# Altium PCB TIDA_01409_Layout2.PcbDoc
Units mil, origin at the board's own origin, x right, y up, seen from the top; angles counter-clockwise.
Board outline 2000 x 1250 mil, 2 copper layers (Top Layer, Bottom Layer), stack 62 mil thick; 42 components, 23 nets, 118 pads, 92 vias.
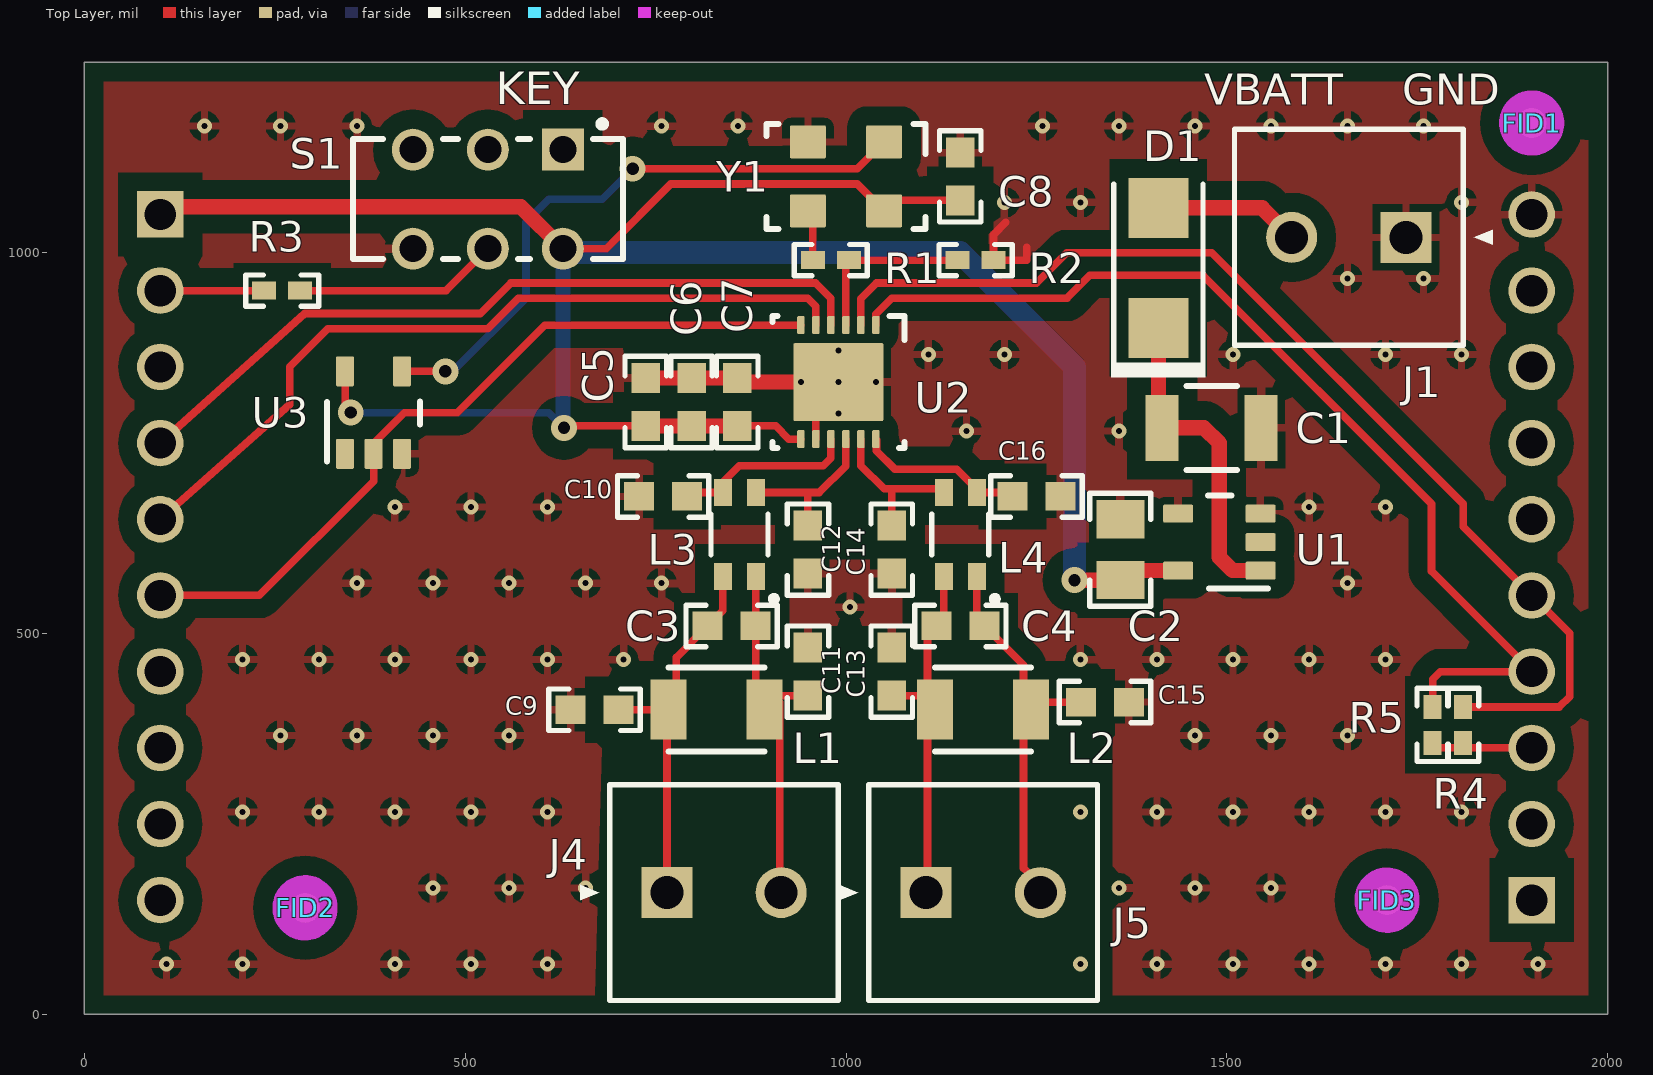
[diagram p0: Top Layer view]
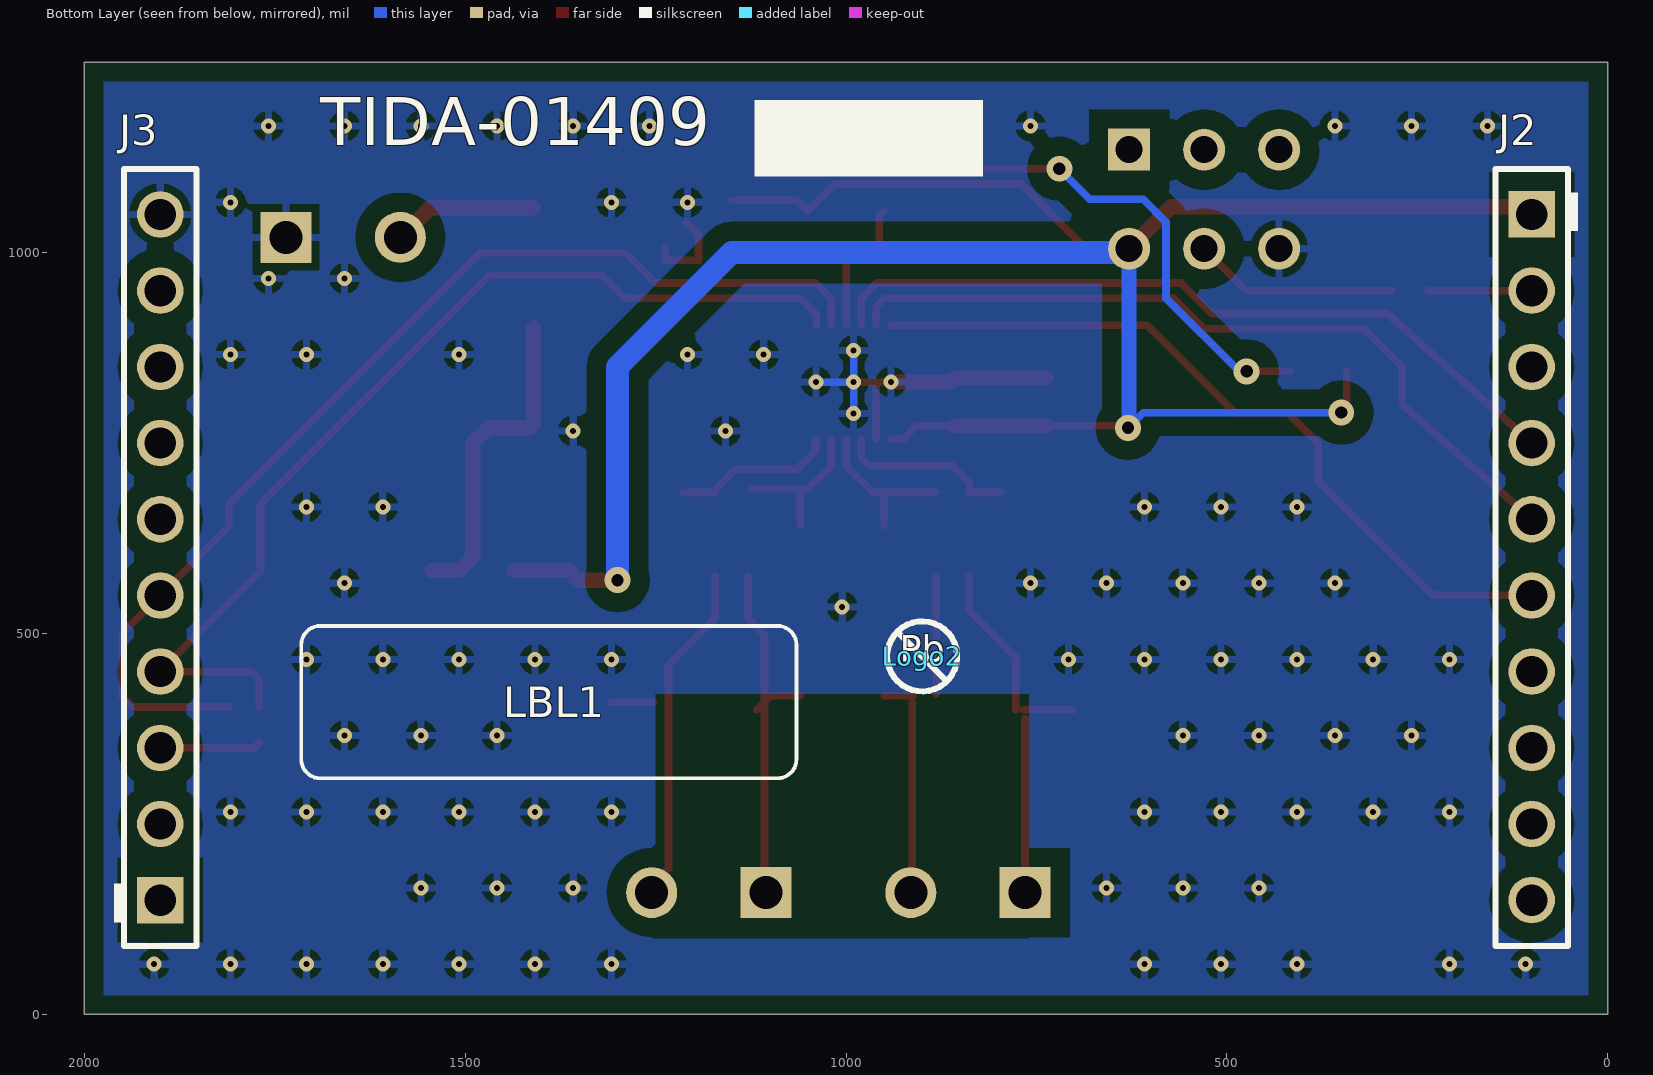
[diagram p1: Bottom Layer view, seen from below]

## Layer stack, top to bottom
Top Solder: solder mask 0.4, Solder Resist, Dk 3.5
Top Layer: signal copper 1.4
Dielectric1: core 59.2, FR-4, Dk 4.8
Bottom Layer: signal copper 1.4
Bottom Solder: solder mask 0.4, Solder Resist, Dk 3.5

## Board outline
0,0 0,1250 2000,1250 2000,0

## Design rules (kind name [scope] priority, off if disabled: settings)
AcuteAngle [All] p1: minimum=4.50000000000000E+0001 checktracksonly=FALSE
AssemblyTestPointUsage [All] p1: valid=2
BoardOutlineClearance BoardOutlineClearance_MountingHoles [OnCopper and InComponentClass('Mounting Holes')] p1: gap=40
BoardOutlineClearance BoardOutlineClearance_Poly [OnCopper and IsPoly] p2: gap=25
BoardOutlineClearance [OnCopper and Not InComponentClass('Logo') and not InComponentClass('FiducialMark') and not InRegion(1000,500,4000,800) and not InPoly] p3: gap=75
Clearance Clearance_Keepouts [((IsTrack Or IsArc) And Not InPoly) And IsFree and IsKeepOut vs ((IsTrack Or IsArc) And Not InPoly) And IsFree and IsKeepOut] p1: gap=0
Clearance Clearance_Poly [InPolygon] p2: gap=25
Clearance [All] p3: gap=7.87
ComponentClearance ComponentClearance_MountingHoles_FiducialMarks [InComponentClass('Mounting Holes') vs InComponentClass('FiducialMark')] p1: gap=50 collisioncheckmode=3 verticalgap=10 showdistances=FALSE
ComponentClearance ComponentClearance_Shunt [InComponentClass('Header') vs InComponentClass('Shunt')] p2: gap=0 collisioncheckmode=3 verticalgap=0 showdistances=FALSE
ComponentClearance ComponentClearance_Logo [InComponentClass('Logo')] p3: gap=50 collisioncheckmode=3 verticalgap=10 showdistances=FALSE
ComponentClearance ComponentClearance_ScrewToNut [(HasFootprint('NY PMS 440 0025 PH')) vs (HasFootprint('Keystone_1902C'))] p4: gap=5 collisioncheckmode=3 verticalgap=10 showdistances=FALSE
ComponentClearance ComponentClearance_MountingHoles [InComponentClass('Mounting Holes')] p5: gap=250 collisioncheckmode=3 verticalgap=100000 showdistances=FALSE
ComponentClearance ComponentClearance_SmallPassives [HasFootprint('0201*') or HasFootprint('0402*') or HasFootprint('0508') or HasFootprint('0603*') or HasFootprint('0612') or HasFootprint('0805*') or HasFootprint('0815*') or HasFootprint('0830*') or HasFootprint('1206*') or HasFootprint('1210*') or HasFootprint('1808*') or HasFootprint('1812*') or HasFootprint('1825*') or HasFootprint('2010*') or HasFootprint('2220*') or HasFootprint('2225*') or HasFootprint('2512*') or HasFootprint('2728*') or HasFootprint('3518*') vs HasFootprint('0201*') or HasFootprint('0402*') or HasFootprint('0508') or HasFootprint('0603*') or HasFootprint('0612') or HasFootprint('0805*') or HasFootprint('0815*') or HasFootprint('0830*') or HasFootprint('1206*') or HasFootprint('1210*') or HasFootprint('1808*') or HasFootprint('1812*') or HasFootprint('1825*') or HasFootprint('2010*') or HasFootprint('2220*') or HasFootprint('2225*') or HasFootprint('2512*') or HasFootprint('2728*') or HasFootprint('3518*')] p6: gap=14.96 collisioncheckmode=3 verticalgap=10 showdistances=FALSE
ComponentClearance ComponentClearance_THtoSMT [IsThruComponent vs IsSMTComponent] p7: gap=40 collisioncheckmode=3 verticalgap=30 showdistances=FALSE
ComponentClearance ComponentClearance_THtoTH [IsThruComponent vs IsThruComponent] p8: gap=30 collisioncheckmode=3 verticalgap=30 showdistances=FALSE
ComponentClearance [All] p9: gap=30 collisioncheckmode=3 verticalgap=10 showdistances=FALSE
DiffPairsRouting [All] p1: maxlimit=100 minlimit=10 mostfreqgap=10 toplayer_minwidth=15 toplayer_maxwidth=15 toplayer_prefwidth=15 bottomlayer_minwidth=15 bottomlayer_maxwidth=15 bottomlayer_prefwidth=15 maxuncoupledlength=1000
FabricationTestPointUsage TestPointUsage [All] p1: valid=2 allowmultiple=FALSE
FabricationTestpoint Testpoint [All] p1: side=3 testpointundercomponent=TRUE minsize=40 maxsize=100 preferedsize=60 minholesize=0 maxholesize=40 preferedholesize=32 testpointgrid=1 allowsidetop=TRUE allowsidebottom=TRUE usegrid=TRUE gridtolerance=0.01
FanoutControl Fanout_LCC [IsLCC] p1: bgadir=Out bgaviamode=Centered fanoutstyle=Auto fanoutdirection=Alternating viagrid=1 // Fanout_LCC (Default Rule)
FanoutControl Fanout_BGA [IsBGA] p2: bgadir=Out bgaviamode=Centered fanoutstyle=Auto fanoutdirection=Alternating viagrid=1 // Fanout_BGA (Default Rule)
FanoutControl Fanout_Default [All] p4: bgadir=Out bgaviamode=Centered fanoutstyle=Auto fanoutdirection=Alternating viagrid=1 // Fanout_Default (Default Rule)
FanoutControl Fanout_Small [(CompPinCount < 5)] p5: bgadir=Out bgaviamode=Centered fanoutstyle=Auto fanoutdirection=OutThenIn viagrid=1 // Fanout_Small (Default Rule)
HoleSize [All] p1: absolutevalues=TRUE maxlimit=251 minlimit=7.87 maxpercent=80.000 minpercent=20.000
MinimumAnnularRing MinimumAnnularRing_ThermalPadVias [IsVia and InAnyComponent] p1: minimumring=5.91
MinimumAnnularRing [All] p2: minimumring=8
MinimumSolderMaskSliver MinimumSolderMaskSliver_Logo [InComponentClass('Logo') vs InComponentClass('Logo')] p1: minsoldermaskwidth=0.7
MinimumSolderMaskSliver [All] p2: minsoldermaskwidth=3.94
PlaneConnect [All] p1: planeconnectstyle=Relief reliefexpansion=10 reliefentries=4 reliefconductorwidth=10 reliefairgap=10
PolygonConnect [All] p1: connectstyle=Relief reliefconductorwidth=10 reliefentries=4 polygonreliefangle="90 Angle" airgapwidth=10
RoutingVias ThermalPadVias [IsVia and InAnyComponent] p1: holewidth=7.87 width=19.68 viastyle="Through Hole" minholewidth=7.87 minwidth=19.68 maxholewidth=12.99 maxwidth=23.62
RoutingVias [All] p2: holewidth=16 width=34 viastyle="Through Hole" minholewidth=7.87 minwidth=26 maxholewidth=40 maxwidth=65
SilkToBoardRegionClearance [Not ((IsComment or IsDesignator) And (Hide <> 'False')) and not InRegion(1000,500,4000,800)] p1:
SilkToSilkClearance SilkToSilkClearance_Pb-FreeLogo [(HasFootprint('Pb-Free_Overlay_Medium') OR HasFootprint('Pb-Free_Overlay_Small')) vs (HasFootprint('Pb-Free_Overlay_Medium') OR HasFootprint('Pb-Free_Overlay_Small'))] p1: silktosilkclearance=0
SilkToSilkClearance [All] p2: silktosilkclearance=4
SilkToSolderMaskClearance SilkToComponentPadClearance [(IsPad or IsFill or IsRegion) and InAnycomponent] p1: minsilkscreentomaskgap=5 clearancetoexposedcopper=TRUE
SilkToSolderMaskClearance "Silk to Solder Mask Opening" [All] p2: minsilkscreentomaskgap=4 clearancetoexposedcopper=FALSE
SolderMaskExpansion [All] p1: expansion=1.97
Width [All] p1: maxlimit=100 minlimit=6 preferedwidth=10 checkconnectedcopper=TRUE
15 further rules are at their usual default settings.

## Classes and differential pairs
component class TIDA_01409_Schematic2: C1 C2 C3 C4 C5 C6 C7 C8 C9 C10 C11 C12 C13 C14 C15 C16 D1 J1 J2 J3 J4 J5 L1 L2 L3 L4 R1 R2 R3 R4 R5 S1 U1 U2 U3 Y1
component class Label: LBL1
component class FiducialMark: FID1 FID2 FID3
component class PCB_Project_EVM_Hardware: FID1 FID2 FID3 LBL1 Logo2 Logo3

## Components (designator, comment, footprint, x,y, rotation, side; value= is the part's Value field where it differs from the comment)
C1 "UMK325AB7106KMHT" 1210_280 1480,770 r0 top
C2 "C2012X7R1A475M125AC" 0805_HV 1360,610 r90 top
C3 "CL10C330FB8NNNC" 0603 850,510 r0 top
C4 "CL10C330FB8NNNC" 0603 1150,510 r0 top
C5 "GRM188R70J105KA01D" 0603 737.27,804 r90 top
C6 "C0603C104K8RACTU" 0603 797.27,804 r90 top
C7 "0603ZC103KAT2A" 0603 857.27,804 r90 top
C8 "0603ZC103KAT2A" 0603 1150,1100 r90 top
C9 "GRM1885C2A180JA01D" 0603 670,400 r180 top
C10 "GRM1885C2A180JA01D" 0603 760,680 r180 top
C11 "GRM1885C2A180JA01D" 0603 950,450 r270 top
C12 "GRM1885C2A180JA01D" 0603 950,610 r90 top
C13 "GRM1885C2A180JA01D" 0603 1060,450 r90 top
C14 "GRM1885C2A180JA01D" 0603 1060,610 r270 top
C15 "GRM1885C2A180JA01D" 0603 1340,410 r180 top
C16 "GRM1885C2A180JA01D" 0603 1250,680 r180 top
D1 "BYS10-45HE3/TR" SMA 1410,980 r90 top
FID1 "Fiducial" Fiducial10-20 1900,1170 r0 top
FID2 "Fiducial" Fiducial10-20 290,140 r0 top
FID3 "Fiducial" Fiducial10-20 1710,150 r0 top
J1 "1727010" PhoenixConact_1727010 1660,1020 r180 top
J2 "SSW-110-01-T-S" Samtec_SSW-110-x1-x-S 100,600 r270 bottom
J3 "SSW-110-01-T-S" Samtec_SSW-110-x1-x-S 1900,600 r90 bottom
J4 "1727010" PhoenixConact_1727010 840,160 r0 top
J5 "1727010" PhoenixConact_1727010 1180,160 r0 top
L1 "CMH322522-180KL" CMH322522 830,400 r0 top
L2 "CMH322522-180KL" CMH322522 1180,400 r0 top
L3 "SRF3216-222Y" SRF3216 860,630 r180 top
L4 "SRF3216-222Y" SRF3216 1150,630 r180 top
LBL1 "Size: 0.65\" x 0.20 \"" Label_650x200 1390,410 r180 bottom
Logo2 "Pb-Free Symbol" Pb-Free_Overlay_Small 900,470 r180 bottom
Logo3 "FCC disclaimer" FCC_disclaimer 1820,1580 r0 top
R1 "ERJ-2GE0R00X" 0402 980,990 r180 top
R2 "CRCW04021K00JNED" 0402 1170,990 r180 top
R3 "CRCW04021K00JNED" 0402 260,950 r0 top
R4 "CRCW040210K0JNED" 0402 1810,380 r270 top
R5 "CRCW040210K0JNED" 0402 1770,380 r270 top
S1 "JS202011CQN" SW_JS202011CQN 530,1070 r270 top
U1 "TPS7B6933QDBVRQ1" DBV0005A_N 1490,620 r180 top
U2 "FDC2212QDNTRQ1" DNT0012B 990,830 r270 top
U3 "SN74LVC1G04QDBVRQ1" DBV0005A_N 380,790 r90 top
Y1 "DSC1001BI1-040.0000" Microchip_DSC1001BI1 1000,1100 r270 top

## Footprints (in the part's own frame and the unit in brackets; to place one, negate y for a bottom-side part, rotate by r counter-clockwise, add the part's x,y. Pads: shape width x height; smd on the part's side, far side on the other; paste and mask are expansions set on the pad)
0402 [mm] "0402 from SM-752 data"
  rect 0.8x0.6 smd: 1(-0.6,0) 2(0.6,0)
  silkscreen extent -1.22,-0.52 1.22,0.52, body extent -0.55,-0.3 0.55,0.3, height 0.6
0603 [mm] "0603 from SM-752 data"
  rect 1x0.95 smd: 1(-0.8,0) 2(0.8,0)
  silkscreen extent -1.52,-0.69 1.52,0.69, body extent -0.87,-0.47 0.87,0.47, height 1
0805_HV [mil] "0805 with 30mil clearance between pads"
  rect 50x63 smd: 1(-40,0) 2(40,0)
  silkscreen extent -74,-40 74,40, body extent -43,-29 43,29, height 57
1210_280 [mm] "SMD, 2-Leads, Body 3.6x2.8mm, Height 2.8mm"
  rect 1.1x2.2 smd: 1(-1.65,0) 2(1.65,0)
  silkscreen extent -0.84,-1.4 0.84,1.4, body extent -1.8,-1.4 1.8,1.4, height 2.8
CMH322522 [mm] "Bourns"
  rect 1.2x2 smd: 1(-1.6,0) 2(1.6,0)
  silkscreen extent -1.6,-1.4 1.6,1.4, body extent -1.7,-1.35 1.7,1.35, height 2.4
DBV0005A_N [mm] "SOT23, 5-Leads, Body 2.9x1.6mm, Pitch 0.95mm, Lead Span 2.8mm, IPC Medium Density"
  rrect17% 1x0.6 smd: 1(-1.375,0.95) 2(-1.375,0) 3(-1.375,-0.95) 4(1.375,-0.95) 5(1.375,0.95)
  silkscreen extent -1.63,-1.55 0.38,1.55, body extent -1.42,-1.46 1.42,1.46, height 1.09
DNT0012B [mm] "SON, 12-Leads, Body 4x4mm, Pitch 0.5mm"
  rrect40% 0.6x0.25 smd: 1(-1.9,1.25) 2(-1.9,0.75) 3(-1.9,0.25) 4(-1.9,-0.25) 5(-1.9,-0.75) 6(-1.9,-1.25) 7(1.9,-1.25) 8(1.9,-0.75) 9(1.9,-0.25) 10(1.9,0.25) 11(1.9,0.75) 12(1.9,1.25)
  rrect4% 2.6x3 smd paste-1.3: 13(0,0)
  silkscreen extent -2.2,-2.2 2.2,2.2, body extent -2,-2 2,2, height 0.81
FCC_disclaimer [mil]
Fiducial10-20 [mm]
  round 1 smd mask+0.5: 1(0,0)
  Top Layer keep-out circle w1.178: c0,0 r0.5
Label_650x200 [mil] "Thermal Transfer Label"
  silkscreen extent -325,-100 325,100, body extent -325,-100 325,100, height 1
Microchip_DSC1001BI1 [mm] "SMD, 4-Leads, Body 5x3.2mm"
  rrect9% 1.1x1.2 smd: 1(-1.15,1.27) 2(-1.15,-1.27) 3(1.15,-1.27) 4(1.15,1.27)
  silkscreen extent -1.75,-2.65 1.75,2.65, body extent -1.6,-2.5 1.6,2.5, height 0.91
Pb-Free_Overlay_Small [mil]
  silkscreen extent -46,-46 46,46
PhoenixConact_1727010 [mm]
  rect 1.7x1.7 hole 1.1: 1(-1.905,0)
  round 1.7 hole 1.1: 2(1.905,0)
  silkscreen extent -4.8,-3.6 3.81,3.6, body extent -3.81,-3.6 3.81,3.7, height 8.52
Samtec_SSW-110-x1-x-S [mm] "Receptacle, 2.54mm, 10x1, TH"
  rect 1.55x1.55 hole 1.04: 1(-11.43,0)
  round 1.55 hole 1.04: 2(-8.89,0) 3(-6.35,0) 4(-3.81,0) 5(-1.27,0) 6(1.27,0) 7(3.81,0) 8(6.35,0) 9(8.89,0) 10(11.43,0)
  silkscreen extent -12.95,-1.21 12.95,1.55, body extent -12.95,-1.21 12.95,1.21, height 8.51
SMA [mm] "Molded Diode, 2-Leads, Body 4.3x2.6mm, IPC Medium Density, based on OnSemi component dimensions and land pattern"
  rect 2x2 smd: 1(-2,0) 2(2,0)
  silkscreen extent -3.66,-1.57 2.79,1.57, body extent -2.6,-1.3 2.6,1.3, height 2.42
SRF3216 [mm] "BOURNS"
  rect 0.6x0.9 smd: 1(-0.55,1.4) 2(-0.55,-1.4) 3(0.55,-1.4) 4(0.55,1.4)
  silkscreen extent -1.25,-0.67 0.95,2.25, body extent -0.9,-1.7 0.9,1.7, height 2.21
SW_JS202011CQN [mm] "C&K components"
  rect 1.4x1.4 hole 0.9 paste+0: 1(-1.65,2.5)
  round 1.4 hole 0.9 paste+0: 2(-1.65,0) 3(-1.65,-2.5) 4(1.65,2.5) 5(1.65,0) 6(1.65,-2.5)
  silkscreen extent -2.61,-4.5 2,4.5, body extent -2,-4.5 2,4.5, height 5.5

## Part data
C1: "CAP, CERM, 10 µF, 50 V, +/- 10%, X7R, AEC-Q200 Grade 1, 1210"
C2: "CAP, CERM, 4.7 µF, 10 V, +/- 20%, X7R, 0805"
C3 C4: "CAP, CERM, 33 pF, 50 V, +/- 5%, C0G/NP0, 0603"
C5: "CAP, CERM, 1 µF, 6.3 V, +/- 10%, X7R, 0603"
C6: "CAP, CERM, 0.1 µF, 10 V, +/- 10%, X7R, 0603"
C7 C8: "CAP, CERM, 0.01 µF, 10 V, +/- 10%, X7R, 0603"
C9 C10 C11 C12 C13 C14 C15 C16: "CAP, CERM, 18 pF, 100 V, +/- 5%, C0G/NP0, 0603"
D1: "Diode, Schottky, 45 V, 1.5 A, AEC-Q101, SMA"
FID1 FID2 FID3: "Fiducial mark.  There is nothing to buy or mount."
J1 J4 J5: "Conn Term Block, 2POS, 3.81mm, TH"
J2 J3: "Receptacle, 2.54mm, 10x1, Tin, TH"
L1 L2: "Inductor, Shielded, Ferrite, 18 µH, 0.12 A, 3.3 ohm, SMD"
L3 L4: "Inductor, Wirewound, Ferrite, 0.2 A, 1.2 ohm, SMD"
LBL1: library part THT-14-423-10, "Thermal Transfer Printable Labels, 0.650\" W x 0.200\" H - 10,000 per roll"
Logo2: library part Pb-Free
Logo3: library part FCC_disclaimer, "FCC_disclaimer"
R1: "RES, 0, 5%, 0.063 W, 0402"
R2 R3: "RES, 1.0 k, 5%, 0.063 W, 0402"
R4 R5: "RES, 10 k, 5%, 0.063 W, 0402"
S1: "Slide Switch, DPDT, 0.3A 6VDC, TH"
U1: "High Voltage Ultra Low Iq - Low Drop Out Regulator, DBV0005A (SOT-5)"
U2: "Multi-Channel 12-Bit or 28-Bit Capacitance-to-Digital Converter (FDC) for Capacitive Sensing, DNT0012B (WSON-12)"
U3: "Automotive Catalog Single Inverter, DBV0005A (SOT-5)"
Y1: "OSC, 4MHz, CMOS, 1.8 to 3.3V, SMD"

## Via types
v1: diameter 19.68, hole 7.87, Top Layer to Bottom Layer, 87 vias
v2: diameter 34, hole 16, Top Layer to Bottom Layer, 5 vias

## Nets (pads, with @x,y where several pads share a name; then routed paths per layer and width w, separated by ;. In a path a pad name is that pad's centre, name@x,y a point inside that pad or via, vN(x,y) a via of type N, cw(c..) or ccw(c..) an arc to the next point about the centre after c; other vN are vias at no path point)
3P3V: C2.1 C5.1 C6.1 C7.1 C8.1 J2.1 S1.4 U1.5 U2.7 U3.5 Y1.4 | length 3181.6
  Top Layer w10: v2@342.6,802.6 U3.5 ; S1.4 685.04,1005.04 770,1090 1014.72,1090 Y1.4 1063.78,1068.5 C8.1 ; v2(630,770) 632.5,772.5 C5.1 ; C7.1 907.5,772.5 924.8,755.2 U2.7 ; C2.1 1350,570 C2.1@1362.6,582.6
  Top Layer w20: J2.1 110,1060 573.46,1060 S1.4 ; C5.1 C6.1 C7.1 ; v2(1300,570) C2.1@1350,570 ; C2.1@1362.6,582.6 U1.5
  Bottom Layer w10: v2(350,790) 610,790 628.43,771.57 v2(630,770) ; S1.4 S1.4@633.46,1000
  Bottom Layer w20: v2@628.43,771.57 S1.4
  Bottom Layer w30: S1.4@633.46,1000 1150,1000 1300,850 v2(1300,570)
ADDR: J2.4 U2.4 | length 1005.2
  Top Layer w10: J2.4 289.56,920 520,920 560,960 960,960 980.16,939.84 U2.4
GND: C1.2 C2.2 C5.2 C6.2 C7.2 C8.2 C9.2 C10.2 C11.1 C12.1 C13.2 C14.2 C15.1 C16.1 J1.1 J3.10 R2.1 S1.6 U1.3 U1.4 U2.8 U2.13 U3.3 Y1.2 | length 571.5
  Top Layer w10: v1(940.79,830) U2.13@960.47,830 ; U2.8 U2.13@960.47,830 ; v1(990,830) U2.13@960.47,830 ; 1209.88,1040 1193.62,1023.74 R2.1 1237.21,990 1237.21,1007.21
  Top Layer w20: C5.2 C6.2 C7.2 ; C7.2@862.76,830 v1(940.79,830)
  Bottom Layer w10: v1(990,788.66) v1(990,830) ; v1(990,871.34) v1(990,830) ; v1(1039.21,830) v1(990,830)
  other v1: 108,66 208,66 408,66 508,66 608,66 1308,66 1408,66 1508,66 1608,66 1708,66 1808,66 1908,66 458,166 558,166 658,166 1358,166 1458,166 1558,166 208,266 308,266 408,266 508,266 608,266 1308,266 1408,266 1508,266 1608,266 1708,266 1808,266 258,366 358,366 458,366 558,366 1458,366 1558,366 1658,366 208,466 308,466 408,466 508,466 608,466 708,466 1308,466 1408,466 1508,466 1608,466 1708,466 1005,535 358,566 458,566 558,566 658,566 758,566 1658,566 408,666 508,666 608,666 1608,666 1708,666 1158,766 1358,766 1108,866 1208,866 1508,866 1708,866 1808,866 1658,966 1758,966 1208,1066 1308,1066 1808,1066 158,1166 258,1166 358,1166 758,1166 858,1166 1258,1166 1358,1166 1458,1166 1558,1166 1658,1166 1758,1166
IN0A: C3.1 C9.1 J4.1 L1.1 L3.4 | length 483.8
  Top Layer w10: C9.1 L1.1 ; J4.1@765,170 L1.1@765,387.99 ; L1.1@777.01,400 777.01,468.5 C3.1 838.35,529.84 L3.4
IN0B: C3.2 C11.2 J4.2 L1.2 L3.1 | length 432.9
  Top Layer w10: L1.2@881.65,421.34 L3.1 ; L1.2@911.5,418.5 C11.2 ; L1.2@912.99,410 912.99,172.01 J4.2@915,170
IN1A: C4.1 C13.1 J5.1 L2.1 L4.4 | length 476.4
  Top Layer w10: C13.1 1098.5,418.5 L2.1@1107.01,410 ; J5.1@1107.01,172.01 L2.1@1107.01,410 ; L2.1 L2.1@1107.01,410 ; L4.4 1128.35,519.84 C4.1 1107.01,498.5 L2.1@1107.01,410
IN1B: C4.2 C15.2 J5.2 L2.2 L4.1 | length 494.9
  Top Layer w10: L4.1 1171.65,519.84 C4.2 1232.99,458.5 1232.99,192.01 J5.2@1255,170 ; L2.2@1252.99,410 C15.2
INTB: J2.5 U2.5 | length 1033.4
  Top Layer w10: J2.5 270,800.44 270,850 320,900 530,900 570,940 950,940 960.47,929.53 U2.5
KEY: J2.2 R3.1 | length 136.4
  Top Layer w10: J2.2 R3.1
NetC10_1: C10.1 L3.3 U2.9 | length 235
  Top Layer w10: C10.1@796.61,685.12 L3.3 838.35,698.35 860,720 970,720 980.16,730.16 U2.9
NetC12_2: C12.2 L3.2 U2.10 | length 211.5
  Top Layer w10: L3.2 950,685.12 ; C12.2 950,685.12 ; U2.10 999.84,719.84 965.12,685.12 950,685.12
NetC14_1: C14.1 L4.3 U2.11 | length 199.8
  Top Layer w10: U2.11 1019.53,720.47 1050,690 1060,690 ; C14.1 1060,690 ; L4.3@1123.46,690 1060,690
NetC16_2: C16.2 L4.2 U2.12 | length 209.8
  Top Layer w10: U2.12 1040,754.41 1040,740 1064.29,715.71 1145.49,715.71 L4.2@1171.65,689.55 ; L4.2 C16.2@1213.39,685.12
NetJ3_3: J3.3 R4.2 R5.2 | length 132.6
  Top Layer w10: R5.2 1776.38,350 J3.3
NetR1_1: R1.1 R2.2 U2.3 | length 229.5
  Top Layer w10: U2.3 999.84,986.22 R1.1 R2.2
NetR1_2: R1.2 Y1.3 | length 67.4
  Top Layer w10: Y1.3 956.38,1048.35 R1.2
NetR3_2: R3.2 S1.5 | length 269.2
  Top Layer w10: R3.2 474.96,950 S1.5
NetU3_4: U3.4 Y1.1 | length 815.9
  Top Layer w10: U3.4 v2(474.13,844.13) ; v2(720,1110) 1014.72,1110 Y1.1
  Bottom Layer w10: v2(474.13,844.13) 484.13,844.13 580,940 580,1040 610,1070 680,1070 v2(720,1110)
SCL: J3.4 R5.1 U2.1 | length 1353.7
  Top Layer w10: U2.1 1039.21,919.21 1060,940 1290,940 1320,970 1468.5,970 1768.5,670 1768.5,581.94 J3.4@1900.44,450 ; R5.1 1770,440 1780,450 J3.4
  Bottom Layer w10: J3.4@1900.44,450 J3.4@1900.44,469.56
SDA: J3.5 R4.1 U2.2 | length 1443.3
  Top Layer w10: U2.2 1019.53,939.53 1040,960 1250,960 1290,1000 1480,1000 1810,670 1810,640.44 1950,500.44 1950,417.24 1936.38,403.62 R4.1
SHUTDOWN: J2.6 U2.6 U3.2 | length 1017
  Top Layer w10: J2.6 230,550 380,700 U3.2 380,750 420,790 490,790 604.8,904.8 U2.6
VBATT: D1.2 J1.2 | length 191
  Top Layer w20: D1.2 1546.26,1058.74 J1.2
VIN: C1.1 D1.1 U1.1 | length 427.9
  Top Layer w10: C1.1@1410,775.04 C1.1
  Top Layer w20: C1.1@1410,775.04 D1.1 ; C1.1 1470,770 1490,750 1490,600 1507.4,582.6 U1.1
pads on no net: FID1.1 FID2.1 FID3.1 J2.3 J2.7 J2.8 J2.9 J2.10 J3.1 J3.2 J3.6 J3.7 J3.8 J3.9 S1.1 S1.2 S1.3 U1.2 U3.1

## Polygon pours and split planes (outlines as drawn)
GND on Bottom Layer "BOTTOM_LAYER_GND_P006" (solid, remove dead copper, pour order 6): 1980,20 1980,1230 20,1230 20,20 1980,20
GND on Top Layer "TOP_LAYER_GND_P008" (solid, remove dead copper, pour order 8): 20,20 20,1230 1980,1230 1980,20 20,20

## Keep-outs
Keep-Out Layer:
  text ".Layer_Name" at 577,-858.49 h60

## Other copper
Top Layer:
  pour cut-out: 1291.61,366.3 1291.61,21.61 1290,20 1350,20 1350,363.11 1353.19,366.3
  pour cut-out: 670,20 671.73,18.27 740,18.27 740,350 730,360 680,360
  pour cut-out: 978.7,596.81 1031.3,596.81 1031.3,688.7 1030,690 990,690 990,608.11
  pour cut-out: 977.27,509.98 1032.73,509.98 1032.73,362.73 1030,360 980,360 980,507.25
  pour cut-out: 1180,330 1290,330 1290,58.27 1330,18.27 1170,18.27 1170,320
  pour cut-out: 943.25,373.82 1068.39,373.82 1070,372.2 1070,350 1090,330 1076.75,316.75 1076.75,218.46 1046.54,218.46 1046.54,101.78 951.31,101.78 943.25,109.83
  pour cut-out: 690,18.27 690,85 706.78,101.78 1260.32,101.78 1260.32,87.95 1330,18.27
  text ".Layer_Name" at 577,-858.49 h60
Bottom Layer:
  pour cut-out: 790,420 760,420 760,410.41 760.41,410 790,410
  pour cut-out: 1255,101.25 1253.75,100 760,100 760,420 769.59,410.41 1250,410.41 1250,106.25
  pour cut-out: 1255,160 765,160 765,405 780,420 1250,420 1250,165
  text ".Layer_Name" at 577,-858.49 h60

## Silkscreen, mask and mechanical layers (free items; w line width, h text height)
Top Overlay:
  text "KEY" at 540,1180 h72.83
  text "VBATT" at 1470,1180 h70
  text "GND" at 1730,1180 h70
  text ".Layer_Name" at 577,-858.49 h60
Bottom Overlay:
  region: 1120,1200 820,1200 820,1100 1120,1100
  text "TIDA-01409" at 1690,1120 h108.27
  text ".Layer_Name" at 577,-858.49 h60
Top Paste:
  text ".Layer_Name" at 577,-858.49 h60
Bottom Paste:
  text ".Layer_Name" at 577,-858.49 h60
Top Solder:
  text ".Layer_Name" at 577,-858.49 h60
  text ".Layer_Name" at 577,-858.49 h60
Bottom Solder:
  text ".Layer_Name" at 577,-858.49 h60
Drill Guide:
  text ".Layer_Name" at 577,-858.49 h60
M1 Board Outline:
  the board outline again, w10
  text ".Layer_Name" at 577,-858.49 h60
M2 Board Dimensions:
  rectangle: 125,-400 500,-275
  rectangle: 0,-275 125,-150
  lines w7: 0,-275 1000,-275 ; 125,-400 125,-150 ; 250,-400 250,-150 ; 500,-400 500,-150 ; 750,-400 750,-150 ; 0,-400 0,-150 1000,-150 1000,-400 0,-400
  text ".Layer_Name" at 577,-858.49 h60
M3 3D STEP Top:
  text ".Layer_Name" at 577,-858.49 h60
M4 3D STEP Bottom:
  text ".Layer_Name" at 577,-858.49 h60
M5 Assembly Top:
  lines w10: -292,-930.17 6308,-930.17 ; -292,-726.83 6310,-726.83 ; -292,-523.5 -292,-1133.5 3713,-1133.5 6310,-1133.5 6310,-523.5 -291.5,-523.5 -291.5,-1133.5 1284,-1133.5 ; 2173,-1133.5 2173,-523.5 ; 3440,-726.83 3440,-523.5 ; 4280,-726.83 4280,-523.5 ; 4902,-1140 4902,-937.17
  text "COMPONENTS MARKED 'DNP' SHOULD NOT BE POPULATED." at 1153.5,-318.5 h60
  text "ASSEMBLY VARIANT:" at 1153,-434 h60
  text ".VariantName" at 2189,-434 h60
  text "PCB VIEWED FROM TOP SIDE" at -228.5,-655.67 h60
  text "BOARD #:" at 2248,-655.67 h60
  text ".PRJ_Number" at 2793.5,-655.67 h60
  text "REV:" at 3638,-655.67 h60
  text ".PCB_Rev" at 3929.5,-655.67 h60
  text "SVN REV:" at 4476,-655.67 h60
  text ".VersionControl_RevNumber" at 4982,-655.67 h60
  text "TID #:" at 2248,-859 h60
  text ".TID" at 2793.5,-859 h60
  text "PLOT NAME =" at -228.5,-1064.34 h60
  text ".plot_File_Name" at 577,-1064.34 h60
  text "GENERATED    :" at 2250,-1064.34 h60
  text ".Print_Date" at 3119.5,-1064.34 h60
  text ".Print_Time" at 3848.5,-1064.34 h60
  text "TEXAS INSTRUMENTS" at 5113,-1064.34 h60
M6 Assembly Bottom:
  lines w10: -292.5,-727.33 6309.5,-727.33 ; -290.5,-930.67 6309.5,-930.67 ; 1115.5,-1140.5 1115.5,-937.67 ; 1737.5,-727.33 1737.5,-524 ; 2577.5,-727.33 2577.5,-524 ; 3844.5,-1134 3844.5,-524 ; 4733.5,-1134 6309,-1134 6309,-524 -292.5,-524 -292.5,-1134 2304.5,-1134 6309.5,-1134 6309.5,-524
  text "COMPONENTS MARKED 'DNP' SHOULD NOT BE POPULATED." at 6102,-318 h60
  text ".VariantName" at 5058,-434 h60
  text "ASSEMBLY VARIANT:" at 6097,-434 h60
  text ".VersionControl_RevNumber" at 1035.5,-656.17 h60
  text "SVN REV:" at 1541.5,-656.17 h60
  text ".PCB_Rev" at 2088,-656.17 h60
  text "REV:" at 2379.5,-656.17 h60
  text ".PRJ_Number" at 3224,-656.17 h60
  text "BOARD #:" at 3769.5,-656.17 h60
  text "PCB VIEWED FROM BOTTOM SIDE" at 6246,-656.17 h60
  text ".TID" at 3224,-859.5 h60
  text "TID #:" at 3769.5,-859.5 h60
  text "TEXAS INSTRUMENTS" at 904.5,-1064.84 h60
  text ".Print_Time" at 2169,-1064.84 h60
  text ".Print_Date" at 2898,-1064.84 h60
  text "GENERATED    :" at 3767.5,-1064.84 h60
  text ".plot_File_Name" at 5440.5,-1064.84 h60
  text "PLOT NAME =" at 6246,-1064.84 h60
M9 Title Sheet:
  drawing of 57 lines, arcs and shapes, not listed
  text "1" at 739.84,8036.5 h70
  text "2" at 3235.5,8036.5 h70
  text "3" at 5724.84,8036.5 h70
  text "4" at 8231.51,8036.5 h70
  text "5" at 10730.5,8036.5 h70
  text "6" at 13235.5,8036.5 h70
  text "A" at -416.5,6893.5 h70
  text "A" at 14383.5,6893.5 h70
  text "B" at -416.5,4513.5 h70
  text "B" at 14383.5,4513.5 h70
  text "C" at -416.5,2138.5 h70
  text "C" at 14383.5,2138.5 h70
  text "PROJECT TITLE:" at 11343.5,277.5 h45
  text "Automotive Capacitive Kick-to-Open" at 11393.5,144.17 h70
  text "DESIGNED FOR:" at 11343.5,-23.5 h45
  text ".PRJ_Customer" at 11393.5,-163.5 h70
  text "D" at -416.5,-231.5 h70
  text "D" at 14383.5,-231.5 h70
  text "FILE NAME:" at 11343.5,-323.5 h45
  text ".PCB_File_Name_No_Path" at 11393.5,-443.5 h70
  text "Texas Instruments (TI) and/or its licensors do not warrant the accuracy or completeness of this specification" at 6374,-605.34 h45
  text "ENGINEER:" at 11343.5,-613.5 h45
  text "LAYOUT BY:" at 12848.5,-613.5 h45
  text "or any information contained therein. TI and/or its licensors do not warrant that this design will meet" at 6329.01,-718 h45
  text "C.Kinnaird" at 11393.5,-768.49 h70
  text "C.Kinnaird" at 12899,-768.49 h70
  text "the specifications, will be suitable for your application or fit for any particular purpose, or will operate in" at 6329.01,-830.67 h45
  text ".Layer_Name" at 577,-858.49 h60
  text "ALTIUM DESIGNER VERSION:" at 12848.5,-923.5 h45
  text "an implementation. TI and/or its licensors do not warrant that the design is production worthy. You should" at 6329.01,-943.33 h45
  text "completely validate and test your design implementation to confirm the system functionality for your application." at 6374,-1056 h45
  text ".print_Scale" at 11393.5,-1056.83 h70
  text ".Application_BuildNumber" at 12899,-1056.83 h70
  text "1" at 739.84,-1263.5 h70
  text "2" at 3235.5,-1263.5 h70
  text "3" at 5724.84,-1263.5 h70
  text "4" at 8231.51,-1263.5 h70
  text "5" at 10730.5,-1263.5 h70
  text "6" at 13235.5,-1263.5 h70
M10 Fab Notes:
  drawing of 173 lines, arcs and shapes, not listed
  text "DESIGN INFORMATION" at 12378.02,6201 h60
  text "MIN. TRACK WIDTH:" at 11733.46,6021 h60
  text "8" at 12829.7,6021 h60
  text "MIL" at 12984.46,6021 h60
  text "MIN. CLEARANCE:" at 11733.46,5889 h60
  text "0.2" at 12769.7,5889 h60
  text "mm" at 12984.46,5889 h60
  text "MIN. VIA PAD SIZE:" at 11733.46,5757 h60
  text "24" at 12799.71,5757 h60
  text "MIL" at 12984.46,5757 h60
  text "0.05mm (2MIL)" at 12428.46,5615.29 h60
  text "MINIMUM ANNULAR RING" at 11404.23,5611 h60
  text "EXTERNAL" at 13136.46,5611 h60
  text "PER" at 11604.23,5493 h60
  text "IPC-D-275 CLASS 2 LEVEL C" at 11824.23,5493 h60
  text "MIL, HOLES" at 13312.46,5380.71 h60
  text "+/-" at 12920,5380 h60
  text "+/-" at 13774,5380 h60
  text "REGISTRATION TOLERANCES:" at 11404.23,5375 h60
  text "METAL" at 12604,5375 h60
  text "5" at 13180.2,5375 h60
  text "3" at 14013.2,5375 h60
  text "MIL" at 14129.46,5375 h60
  text "+/-" at 13774,5262 h60
  text "HOLE SIZE TOLERANCE (UNLESS OTHERWISE SPECIFIED):" at 11404.23,5257 h60
  text "3" at 14013.2,5257 h60
  text "MIL" at 14129.46,5257 h60
  text "MATERIAL:" at 11329.46,5047.54 h60
  text "FR-4 High Tg" at 12315.9,4907.21 h60
  text "FR-408" at 11750.46,4898.64 h60
  text "OTHER" at 13238.46,4898.64 h60
  text "X" at 12161,4895 h60
  text "62 MIL (1.6mm) +/-10%" at 12070.56,4735.92 h60
  text "THICKNESS:" at 11404.23,4731.64 h60
  text "X" at 11942.4,4731.64 h60
  text "OTHER" at 13355.46,4731.64 h60
  text "TOLERANCE:" at 11404.23,4573.64 h60
  text "X" at 12243.53,4573.64 h60
  text "ANSI IPC-6012 TYPE 3 CLASS 2" at 12430.48,4573.64 h60
  text "OTHER +/-" at 12430.46,4417.64 h60
  text "BOW & TWIST:" at 11404.23,4260.64 h60
  text "X" at 12243.53,4260.64 h60
  text "ANSI IPC-6012 TYPE 3 CLASS 2" at 12430.48,4260.64 h60
  text "OTHER +/-" at 12430.46,4102.13 h60
  text "DRILLING:" at 11329.46,3963.64 h60
  text "REFERENCE:" at 11404.23,3846.64 h60
  text "X" at 12052.46,3846.64 h60
  text "AS SHOWN" at 12239.46,3846.64 h60
  text "X" at 12953.46,3846.64 h60
  text "NC_DRILL FILES" at 13090.46,3846.64 h60
  text "PTH COPPER THICKNESS:" at 11404.23,3688.64 h60
  text "X" at 12534.46,3688.64 h60
  text "20-30 um" at 12671.46,3688.64 h60
  text "OTHER" at 13388.46,3688.64 h60
  text "BOARD FINISH:" at 11329.46,3529.64 h60
  text "SILKSCREEN:" at 11484.68,3411.64 h60
  text "X" at 12433.46,3411.64 h60
  text "TOP" at 12559.46,3411.64 h60
  text "X" at 12943.46,3411.64 h60
  text "BOTTOM" at 13070.46,3411.64 h60
  text "SILKSCREEN COLOR:" at 11484.68,3244.64 h60
  text "X" at 12432.42,3244.64 h60
  text "WHITE" at 12559.46,3244.64 h60
  text "OTHER" at 13070.46,3244.64 h60
  text "X" at 12563.42,3085.44 h60
  text "GREEN" at 12690.46,3085.44 h60
  text "OTHER" at 13308.46,3085.44 h60
  text "SOLDER RESIST COLOR:" at 11484.68,3074.64 h60
  text "X" at 12563.42,2915.44 h60
  text "MATTE" at 12690.46,2915.44 h60
  text "SEMI-GLOSS" at 13308,2914.8 h60
  text "IMMERSION GOLD (ENIG)" at 12390.46,2726.92 h60
  text "ENEPIG" at 13728,2723.64 h60
  text "SURFACE FINISH:" at 11329.46,2722.64 h60
  text "X" at 12203.51,2722.64 h60
  text "IMM. TIN/SILVER OR EQUIV" at 11659,2565.64 h60
  text "OTHER" at 13090.46,2565.64 h60
  text "ARRAY/PANEL:" at 11329.46,2386.64 h60
  text "CUT AND TRIM PER M1 BOARD OUTLINE" at 12390.46,2382.35 h60
  text "N.C. ROUTE" at 12390.46,2230.64 h60
  text "X" at 13069.46,2230.64 h60
  text "V. SCORE" at 13256.46,2230.64 h60
  text "CERTIFICATION:" at 11329.46,2093.64 h60
  text "MATERIALS AND WORKMANSHIP FOR ALL PCBS" at 12054.46,2093.64 h60
  text "TO MEET OR EXCEED THE REQUIREMENTS OF:" at 12054.46,1995.64 h60
  text "X" at 11680.96,1859.13 h60
  text "ANSI IPC-A-600F CLASS ->" at 11819.96,1859.13 h60
  text "X" at 13459.02,1859.13 h60
  text "2" at 13577.96,1859.14 h60
  text "1" at 13262.96,1857.64 h60
  text "3" at 13931.96,1857.64 h60
  text "X" at 12495.02,1699.64 h60
  text "RoHS" at 12631.96,1699.64 h60
  text "OTHER" at 13276.36,1699.64 h60
  text "PER ORDER" at 13673.42,1699.64 h60
  text "ALL BOARDS MUST MEET OR EXCEED UL94-V0 REQUIREMENTS." at 11357,1534 h60
  text "PCB MUST BEAR THE UL94V-0 UL REGISTERED MATERIAL ID NUMBER" at 11357,1414 h60
  text "ADDITIONAL REQUIREMENTS:" at 11329.46,1240.64 h60
  text "MICROSECTION:" at 11404.23,1125.64 h60
  text "YES" at 12309.96,1125.64 h60
  text "REQUIRED" at 13171.46,969.49 h60
  text "BARE BOARD ELEC. TEST:" at 11404.23,966.64 h60
  text "NONE" at 12709.96,966.64 h60
  text "X" at 13044.46,966.64 h60
  text "PER ORDER" at 13763.46,966.64 h60
  text ".Layer_Name" at 577,-858.49 h60
M11 Gerber Information:
  lines w10: -292,-930.17 6308,-930.17 ; -292,-726.83 6310,-726.83 ; -292,-523.5 -292,-1133.5 3713,-1133.5 6310,-1133.5 6310,-523.5 -291.5,-523.5 -291.5,-1133.5 1284,-1133.5 ; 2173,-1133.5 2173,-523.5 ; 3440,-726.83 3440,-523.5 ; 4280,-726.83 4280,-523.5 ; 4902,-1140 4902,-937.17
  text "ALL ARTWORK VIEWED FROM TOP SIDE" at -228.5,-655.67 h60
  text "BOARD #:" at 2248,-655.67 h60
  text ".PRJ_Number" at 2793.5,-655.67 h60
  text "REV:" at 3638,-655.67 h60
  text ".PCB_Rev" at 3929.5,-655.67 h60
  text "SVN REV:" at 4476,-655.67 h60
  text ".VersionControl_RevNumber" at 4982,-655.67 h60
  text "LAYER NAME =" at -228.5,-858.49 h60
  text "TID #:" at 2248,-859 h60
  text ".TID" at 2793.5,-859 h60
  text "PLOT NAME =" at -228.5,-1064.34 h60
  text ".plot_File_Name" at 577,-1064.34 h60
  text "GENERATED    :" at 2250,-1064.34 h60
  text ".Print_Date" at 3119.5,-1064.34 h60
  text ".Print_Time" at 3848.5,-1064.34 h60
  text "TEXAS INSTRUMENTS" at 5113,-1064.34 h60
M12 Stackup:
  drawing of 191 lines, arcs and shapes, not listed
  text "Layer" at 9790.34,7830 h60
  text "Name" at 10200.26,7830 h60
  text "Material" at 11130,7830 h60
  text "Thickness" at 11989.77,7830 h60
  text "Constant" at 12639.6,7830 h60
  text "Board Layer Stack" at 13209.46,7830 h60
  text "1" at 9790.34,7710 h60
  text "Top Overlay" at 10200.26,7710 h60
  text "2" at 9790.34,7590 h60
  text "Top Solder" at 10200.26,7590 h60
  text "Solder Resist" at 11130,7590 h60
  text "0.40mil" at 11989.77,7590 h60
  text "3.5" at 12639.6,7590 h60
  text "3" at 9790.34,7470 h60
  text "Top Layer" at 10200.26,7470 h60
  text "Copper" at 11130,7470 h60
  text "1.40mil" at 11989.77,7470 h60
  text "4" at 9790.34,7350 h60
  text "Dielectric1" at 10200.26,7350 h60
  text "FR-4" at 11130,7350 h60
  text "59.20mil" at 11989.77,7350 h60
  text "4.8" at 12639.6,7350 h60
  text "5" at 9790.34,7230 h60
  text "Bottom Layer" at 10200.26,7230 h60
  text "Copper" at 11130,7230 h60
  text "1.40mil" at 11989.77,7230 h60
  text "6" at 9790.34,7110 h60
  text "Bottom Solder" at 10200.26,7110 h60
  text "Solder Resist" at 11130,7110 h60
  text "0.40mil" at 11989.77,7110 h60
  text "3.5" at 12639.6,7110 h60
  text "7" at 9790.34,6990 h60
  text "Bottom Overlay" at 10200.26,6990 h60
  text ".Layer_Name" at 577,-858.49 h60
M13 Component Bodies Top:
  text ".Layer_Name" at 577,-858.49 h60
M14 Component Bodies Bottom:
  text ".Layer_Name" at 577,-858.49 h60
M15 Courtyards Top:
  text ".Layer_Name" at 577,-858.49 h60
M16 Courtyards Bottom:
  text ".Layer_Name" at 577,-858.49 h60
Drill Drawing:
  lines w10: 5326.65,2883.79 5370.8,2883.79 5370.8,2927.94 5326.65,2927.94 5326.65,2883.79 ; 5326.65,3027.27 5370.8,3027.27 5348.73,2983.12 5326.65,3027.27 ; 5326.65,3093.5 5337.69,3093.5 5348.73,3082.46 5359.76,3093.5 5370.8,3093.5 5359.76,3104.53 5370.8,3115.57 5359.76,3115.57 5348.73,3126.61 5337.69,3115.57 5326.65,3115.57 5337.69,3104.53 5326.65,3093.5 ; 5326.65,3181.8 5370.8,3181.8 5370.8,3225.94 5326.65,3225.94 5326.65,3181.8 ; 5326.65,3281.13 5326.65,3292.17 5337.69,3303.2 5326.65,3314.24 5326.65,3325.28 5337.69,3325.28 5348.73,3314.24 5359.76,3325.28 5370.8,3325.28 5370.8,3314.24 5359.76,3303.2 5370.8,3292.17 5370.8,3281.13 5359.76,3281.13 5348.73,3292.17 5337.69,3281.13 5326.65,3281.13 ; 5335.48,3190.62 5361.97,3190.62 5361.97,3217.11 5335.48,3217.11 5335.48,3190.62
  lines w12: 5286,2853.99 8396.01,2853.99 ; 5286,3350.66 8396.01,3350.66 ; 5601.13,2754.65 5601.13,3450 ; 5918.04,2754.65 5918.04,3450 ; 6539.09,2754.65 6539.09,3450 ; 6783.08,2754.65 6783.08,3450 ; 7143.01,2754.65 7143.01,3450 ; 7852.45,2754.65 7852.45,3450 ; 5286,2754.65 8396.01,2754.65 8396.01,3450 5286,3450 5286,2754.65
  text "Symbol" at 5345.6,3380.47 h72
  text "Quantity" at 5630.93,3380.47 h72
  text "Finished Hole Size" at 5947.84,3380.47 h72
  text "Plated" at 6568.9,3380.47 h72
  text "Hole Type" at 6812.88,3380.47 h72
  text "Drill Layer Pair" at 7172.81,3380.47 h72
  text "Hole Tolerance" at 7882.26,3380.47 h72
  text "87" at 5630.93,3281.13 h60
  text "7.87mil (0.200mm)" at 5947.84,3281.13 h60
  text "PTH" at 6568.9,3281.13 h60
  text "Round" at 6812.88,3281.13 h60
  text "Top Layer - Bottom Layer" at 7172.81,3281.13 h60
  text "5" at 5630.93,3181.8 h60
  text "16.00mil (0.406mm)" at 5947.84,3181.8 h60
  text "PTH" at 6568.9,3181.8 h60
  text "Round" at 6812.88,3181.8 h60
  text "Top Layer - Bottom Layer" at 7172.81,3181.8 h60
  text "6" at 5630.93,3082.46 h60
  text "35.43mil (0.900mm)" at 5947.84,3082.46 h60
  text "PTH" at 6568.9,3082.46 h60
  text "Round" at 6812.88,3082.46 h60
  text "Top Layer - Bottom Layer" at 7172.81,3082.46 h60
  text "20" at 5630.93,2983.12 h60
  text "40.94mil (1.040mm)" at 5947.84,2983.12 h60
  text "PTH" at 6568.9,2983.12 h60
  text "Round" at 6812.88,2983.12 h60
  text "Top Layer - Bottom Layer" at 7172.81,2983.12 h60
  text "6" at 5630.93,2883.79 h60
  text "43.31mil (1.100mm)" at 5947.84,2883.79 h60
  text "PTH" at 6568.9,2883.79 h60
  text "Round" at 6812.88,2883.79 h60
  text "Top Layer - Bottom Layer" at 7172.81,2883.79 h60
  text "124 Total" at 5630.93,2784.45 h60
  text ".Layer_Name" at 577,-858.49 h60
M17 Embedded Cavity:
  text ".Layer_Name" at 577,-858.49 h60
M18 Embedded Assembly:
  text ".Layer_Name" at 577,-858.49 h60
M19 Embedded Keepout:
  text ".Layer_Name" at 577,-858.49 h60

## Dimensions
0,0 to 0,1250 on M2 Board Dimensions
0,0 to 2000,0 on M2 Board Dimensions
0,-400 to 1000,-400 on M2 Board Dimensions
